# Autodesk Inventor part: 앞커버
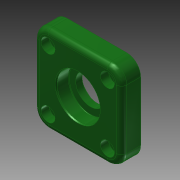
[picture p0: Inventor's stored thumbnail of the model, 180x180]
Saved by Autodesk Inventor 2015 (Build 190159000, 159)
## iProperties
Created: 2018-07
Part Number: 앞커버
Material: 알루미늄 6061
Document SubType Name: Modeling
Designer: mduedu
Density: 1 g/cm^3
Appearance: 매끄러움 - 짙은 산림 녹색
Author: mduedu
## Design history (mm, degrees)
sketch "스케치1"
  geometry: C1 r 16 at (0, 0); 1 further point
  constraints: 1 centre point, 1 coincident
  dimensions: "d0" = 32 diameter of C1
extrude "돌출1" new body sketch "스케치1" distance "d1" = 3; taper "d2" = 0 deg
sketch "스케치2"
  geometry: L1 (-25, -25)-(25, -25); L2 (25, -25)-(25, 25); L3 (25, 25)-(-25, 25); L4 (-25, 25)-(-25, -25); L5 (-25, -25)-(25, 25); L6 (25, -25)-(-25, 25); 1 further point
  constraints: 12 end point, 2 midpoint, 2 parallel, 1 horizontal, 1 perpendicular
  dimensions: "d3" = 50 distance of L3.end L2.end; "d4" = 50 distance of L2.end L1.end
extrude "돌출2" join sketch "스케치2" distance "d5" = 11; taper "d6" = 0 deg
hole "구멍1" diameter "d9" = 25; stored, may be unused: countersink angle "d13" = 90 deg, drill point angle "d15" = 0 deg; dims "d7" = 10, "d8" = 10, "d10" = 6, "d11" = 4, "d12" = 2, "d14" = 3
sketch "스케치3"
  geometry: C1 r 12.5 at (0, 0); 1 further point
  constraints: 1 centre point, 1 coincident
  dimensions: "d16" = 25 diameter of C1
extrude "돌출3" cut sketch "스케치3" distance "d17" = 7.3; taper "d18" = 0 deg
sketch "스케치4"
  geometry: C1 r 8.5 at (0, 0); 1 further point
  constraints: 1 centre point, 1 coincident
  dimensions: "d19" = 17 diameter of C1
extrude "돌출4" cut sketch "스케치4" stored distance "d20" = 7.3; taper "d21" = 0 deg
chamfer "모따기1" distance "d22" = 0.7; stored, may be unused: second distance "d23" = 2, angle "d24" = 30 deg
fillet "모깎기1" dims "d25" = 0.3
fillet "모깎기2" dims "d26" = 3
fillet "모깎기3" dims "d27" = 8
sketch "스케치5"
  geometry: L1 (25, -17)-(25, 17) reference; L2 (17, 25)-(-17, 25) reference; L3 (-25, 17)-(-25, -17) reference; L4 (-17, -25)-(17, -25) reference; C1 r 12.904 at (0, 0) reference; A1 r 8 centre (17, -17) between (17, -25) and (25, -17) reference; A2 r 8 centre (17, 17) between (25, 17) and (17, 25) reference; A3 r 8 centre (-17, 17) between (-17, 25) and (-25, 17) reference; A4 r 8 centre (-17, -17) between (-25, -17) and (-17, -25) reference; 5 further points
  constraints: 4 coincident
hole "구멍2" sketch "스케치5" at (-17, 17), (17, 17), (17, -17), (-17, -17) diameter "d28" = 4.5; stored, may be unused: countersink angle "d32" = 90 deg, drill point angle "d34" = 0 deg; dims "d29" = 6, "d30" = 8, "d31" = 4.6, "d33" = 3
fillet "모깎기4" dims "d35" = 3
chamfer "모따기2" distance "d36" = 1; stored, may be unused: second distance "d37" = 2, angle "d38" = 45 deg
node "솔리드1"
node "투영된 루프1"
